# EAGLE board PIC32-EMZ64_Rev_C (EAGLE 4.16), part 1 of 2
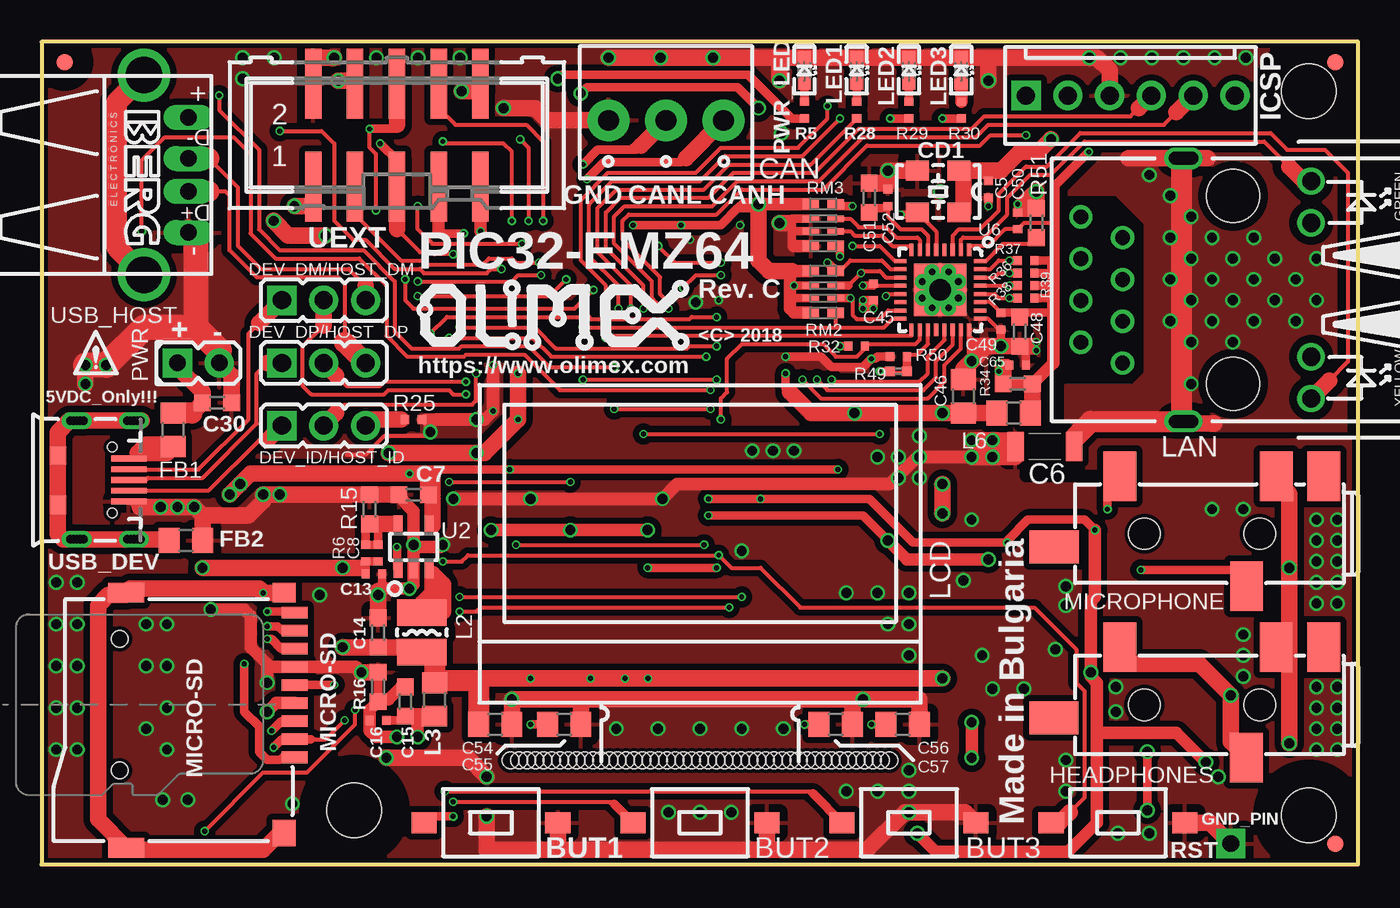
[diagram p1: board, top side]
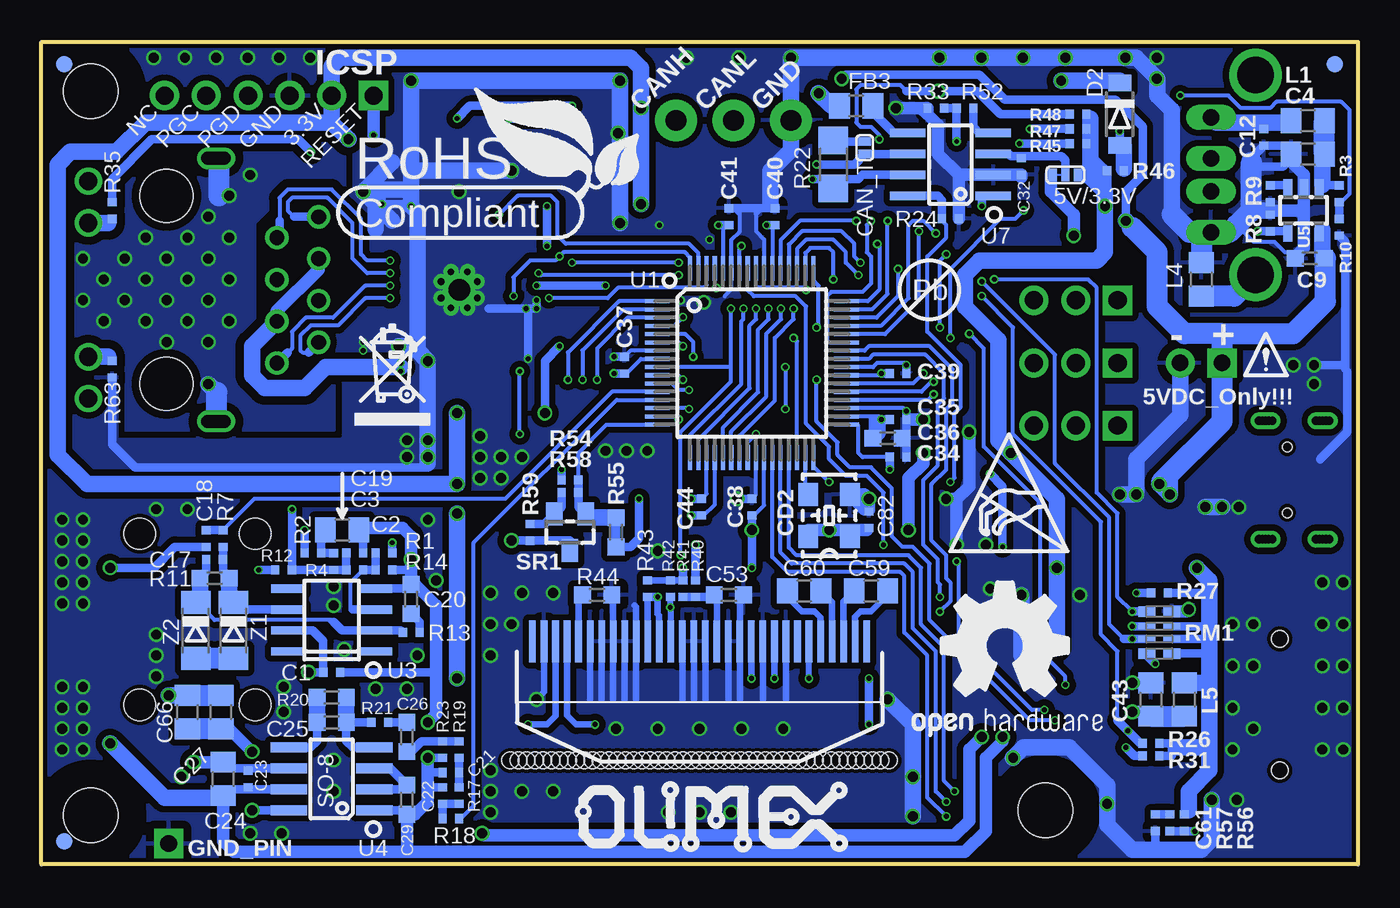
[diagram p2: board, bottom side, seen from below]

Size 80 x 50 mm. Coordinates in mm from the lower left corner, seen from the top.
Outline: 0,0 80,0 80,50 0,50 0,0
Copper layers (1*16): Top 0.035mm / dielectric 1.5mm / Bottom 0.035mm
Design rules "default": minimum track width 5mil, minimum drill 0.3mm, track to track 8mil, track to pad 8mil, pad to pad 8mil, via to via 8mil, smd to smd 1mil, copper to edge 10mil, drill to drill 8mil, minimum pad ring 10mil, minimum via ring 4mil, stop-mask expansion 4mil, vias tented up to drill 25mil, thermal gap 20mil
Net classes: 1 PWR: width 0.203 mm, drill 0.178 mm, clearance 0.381 mm; 2 thin: width 0.127 mm, drill 0.127 mm
Holes 3.3 mm at 19,3.3 77,3 77,47
tRestrict: area 74,44 to 80,50; area 16,0.3 to 22,6.3; area 74,0 to 80,6; 4 lines
bRestrict: area 16,0.3 to 22,6.3; area 74,0 to 80,6; area 74,44 to 80,50

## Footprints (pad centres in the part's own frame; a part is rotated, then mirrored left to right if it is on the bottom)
SJ_2_SMALLER_12_TIED = smd 0.508 x 0.762: 1 -0.762,0; 2 0,0; 3 0.762,0
WS-TAKT_6X3.5_SMD_NOCREAM = smd 1.27 x 1.524: P$1 0,4.064; P$2 0,-4.064
C0402_SMALL = smd 0.5 x 0.55: 1 -0.508,0; 2 0.508,0
C0805_5MIL_DWS = smd 1.27 x 1.524: 1 -1.016,0; 2 1.016,0
C1206_5MILS_WS_ISO = smd 1.016 x 1.778: 1 -1.778,0; 2 1.778,0
C0603_DWS = smd 1.016 x 1.016: 1 -0.889,0; 2 0.889,0
CON3/3.5MM = drill 1.27 pad 2.54 round: 1 -1.75,-0.5; 2 1.75,-0.5; 3 5.25,-0.5
SJ_1_SMALLER = smd 0.508 x 0.762: 1 -0.381,0; 2 0.381,0
5032-4P_HCX-3S = smd 1.4 x 1.2: 1 -1.27,-1.27; 2 1.27,-1.27; 3 1.27,1.27; 4 -1.27,1.27
SOD-123 = smd 1 x 1.4: A 1.9,0; C -1.9,0
JP2 = drill 1.1 pad 1.778 square: 1 -2.54,0 | drill 1.1 pad 1.778 round: 2 0,0; 3 2.54,0
L0805_5MIL_DWS = smd 1.27 x 1.524: 1 -1.016,0; 2 1.016,0
FIDUCIAL-1X3 = smd 1 x 1: 1 0,0
TEST_PAD40/70/SQUARE = drill 1.016 pad 1.778 square: P$1 0,0
PJ-W47S-05D2-LF_5PIN_V2 = smd 2 x 3: 1 2.1,-0.5; 2 14.5,-0.5; 3 6.8,6.2; 5 5,-0.5 | smd 3 x 2: 4 18.5,3.8 | hole 1.9: 6,3; 13,3
CON2.54MM-6-0D = drill 1.092 pad 1.778 square: 1 -6.35,0 | drill 1.092 pad 1.778 round: 2 -3.81,0; 3 -1.27,0; 4 1.27,0; 5 3.81,0; 6 6.35,0
CD32 = smd 1.6 x 3: 1 -1.2,0; 2 1.2,0
RJLBC-060TC1_MILLING = drill 0.9 round: 1 -4.455,6.7; 2 -3.185,9.24; 3 -1.915,6.7; 4 -0.645,9.24; 5 0.625,6.7; 6 1.895,9.24; 7 3.165,6.7; 8 4.435,9.24 | drill 0.8 round: _1 -8,2.5; _2 -8,2.7; _3 -8,2.9; _4 -8,3.3; _5 -8,3.5; _6 8,3.5; _7 8,3.3; _8 8,2.9; _9 8,2.7; _10 8,2.5; GND1 -8,3.1; GND2 8,3.1 | drill 1.1 round: AG 4.07,-4.748; AY -6.61,-4.748; KG 6.61,-4.748; KY -4.07,-4.748 | hole 3.2: -5.715,0; 5.715,0
IROP055-010-0128064-W(BOTTOM_CONTACTS_DRILLING) = smd 0.4 x 2.54 bottom: 1 -10.15,-6.77; 2 -9.45,-6.77; 3 -8.75,-6.77; 4 -8.05,-6.77; 5 -7.35,-6.77; 6 -6.65,-6.77; 7 -5.95,-6.77; 8 -5.25,-6.77; 9 -4.55,-6.77; 10 -3.85,-6.77; 11 -3.15,-6.77; 12 -2.45,-6.77; 13 -1.75,-6.77; 14 -1.05,-6.77; 15 -0.35,-6.77; 16 0.35,-6.77; 17 1.05,-6.77; 18 1.75,-6.77; 19 2.45,-6.77; 20 3.15,-6.77; 21 3.85,-6.77; 22 4.55,-6.77; 23 5.25,-6.77; 24 5.95,-6.77; 25 6.65,-6.77; 26 7.35,-6.77; 27 8.05,-6.77; 28 8.75,-6.77; 29 9.45,-6.77; 30 10.15,-6.77 | hole 1: -11,-14; -10.5,-14; -10,-14; -9.5,-14; -9,-14; -8.5,-14; -8,-14; -7.5,-14; -7,-14; -6.5,-14; -6,-14; -5.5,-14; -5,-14; -4.5,-14; -4,-14; -3.5,-14; -3,-14; -2.5,-14; -2,-14; -1.5,-14; -1,-14; -0.5,-14; 0,-14; 0.5,-14; 1,-14; 1.5,-14; 2,-14; 2.5,-14; 3,-14; 3.5,-14; 4,-14; 4.5,-14; 5,-14; 5.5,-14; 6,-14; 6.5,-14; 7,-14; 7.5,-14; 8,-14; 8.5,-14; 9,-14; 9.5,-14; 10,-14; 10.5,-14; 11,-14; -11.5,-14; 11.5,-14
LED-0603_TEST = smd 0.8 x 0.8: A 0.762,0; C -0.762,0
TFC-WPAPR-08 = smd 1.6 x 0.7: 1 -6.994,2.25; 2 -6.994,1.15; 3 -6.994,0.05; 4 -6.994,-1.05; 5 -6.994,-2.15; 6 -6.994,-3.25; 7 -6.994,-4.35; 8 -6.994,-5.45; 9 -6.994,-6.55 | smd 1.4 x 1.2: 10 -6.369,-7.75 | smd 1.4 x 1.6: 11 -6.369,6.85 | smd 2.2 x 1.2: 12 3.231,-7.75; 13 3.231,7.75 | hole 1: 3.631,-4.95; 3.631,3.05
HN1X2 = drill 1 pad 1.778 square: 1 -1.27,0 | drill 1 pad 1.778 round: 2 1.27,0
R0402_SMALL = smd 0.5 x 0.55: 1 -0.508,0; 2 0.508,0
R0603_5MIL_DWS = smd 1.016 x 1.016: 1 -0.889,0; 2 0.889,0
0603_0R = smd 1.016 x 1.016: 1 -0.889,0; 2 0.889,0
R1206_5MIL_WS = smd 1.651 x 1.778: 1 -1.46,0; 2 1.46,0
R0402_TI_0R = smd 0.61 x 0.584: 1 -0.508,0; 2 0.508,0
R_MATRIX_4 = smd 0.635 x 1.016: 1.1 -1.27,-0.762; 1.2 -1.27,0.762; 4.1 1.27,-0.762; 4.2 1.27,0.762 | smd 0.381 x 1.016: 2.1 -0.381,-0.762; 2.2 -0.381,0.762; 3.1 0.381,-0.762; 3.2 0.381,0.762
SOT-23 = smd 1.4 x 1: 1 1.1,-0.95; 2 1.1,0.95; 3 -1.1,0
TQFP64-1 = smd 0.25 x 1.5: 1 -3.75,-5.75; 2 -3.25,-5.75; 3 -2.75,-5.75; 4 -2.25,-5.75; 5 -1.75,-5.75; 6 -1.25,-5.75; 7 -0.75,-5.75; 8 -0.25,-5.75; 9 0.25,-5.75; 10 0.75,-5.75; 11 1.25,-5.75; 12 1.75,-5.75; 13 2.25,-5.75; 14 2.75,-5.75; 15 3.25,-5.75; 16 3.75,-5.75; 33 3.75,5.75; 34 3.25,5.75; 35 2.75,5.75; 36 2.25,5.75; 37 1.75,5.75; 38 1.25,5.75; 39 0.75,5.75; 40 0.25,5.75; 41 -0.25,5.75; 42 -0.75,5.75; 43 -1.25,5.75; 44 -1.75,5.75; 45 -2.25,5.75; 46 -2.75,5.75; 47 -3.25,5.75; 48 -3.75,5.75 | smd 1.5 x 0.25: 17 5.75,-3.75; 18 5.75,-3.25; 19 5.75,-2.75; 20 5.75,-2.25; 21 5.75,-1.75; 22 5.75,-1.25; 23 5.75,-0.75; 24 5.75,-0.25; 25 5.75,0.25; 26 5.75,0.75; 27 5.75,1.25; 28 5.75,1.75; 29 5.75,2.25; 30 5.75,2.75; 31 5.75,3.25; 32 5.75,3.75; 49 -5.75,3.75; 50 -5.75,3.25; 51 -5.75,2.75; 52 -5.75,2.25; 53 -5.75,1.75; 54 -5.75,1.25; 55 -5.75,0.75; 56 -5.75,0.25; 57 -5.75,-0.25; 58 -5.75,-0.75; 59 -5.75,-1.25; 60 -5.75,-1.75; 61 -5.75,-2.25; 62 -5.75,-2.75; 63 -5.75,-3.25; 64 -5.75,-3.75
SOT23-5 = smd 1.2 x 0.55: 1 1.3,-0.95; 2 1.3,0; 3 1.3,0.95; 4 -1.3,0.95; 5 -1.3,-0.95
SO08 = smd 0.508 x 2.032: 1 -1.905,-2.667; 2 -0.635,-2.667; 3 0.635,-2.667; 4 1.905,-2.667; 5 1.905,2.667; 6 0.635,2.667; 7 -0.635,2.667; 8 -1.905,2.667
SO-8 = smd 0.6 x 2.2: 1 -1.905,-2.6; 2 -0.635,-2.6; 3 0.635,-2.6; 4 1.905,-2.6; 5 1.905,2.6; 6 0.635,2.6; 7 -0.635,2.6; 8 -1.905,2.6
QFN-32(DRILLS) = smd 0.25 x 0.75: 1 -1.75,-2.425; 2 -1.25,-2.425; 3 -0.75,-2.425; 4 -0.25,-2.425; 5 0.25,-2.425; 6 0.75,-2.425; 7 1.25,-2.425; 8 1.75,-2.425; 17 1.75,2.425; 18 1.25,2.425; 19 0.75,2.425; 20 0.25,2.425; 21 -0.25,2.425; 22 -0.75,2.425; 23 -1.25,2.425; 24 -1.75,2.425 | smd 0.75 x 0.25: 9 2.425,-1.75; 10 2.425,-1.25; 11 2.425,-0.75; 12 2.425,-0.25; 13 2.425,0.25; 14 2.425,0.75; 15 2.425,1.25; 16 2.425,1.75; 25 -2.425,1.75; 26 -2.425,1.25; 27 -2.425,0.75; 28 -2.425,0.25; 29 -2.425,-0.25; 30 -2.425,-0.75; 31 -2.425,-1.25; 32 -2.425,-1.75 | drill 1.3 round: EP1 0,0 | drill 0.4 round: EP2 -0.5,1.1; EP3 0.5,1.1; EP4 1.1,0.5; EP5 1.1,-0.5; EP6 0.5,-1.1; EP7 -0.5,-1.1; EP8 -1.1,-0.5; EP9 -1.1,0.5 | smd 3.2 x 3.2: EXP_PAD 0,0
SO-08_THIN = smd 0.508 x 2.159: 1 -1.905,-2.603; 2 -0.635,-2.603; 3 0.635,-2.603; 4 1.905,-2.603; 5 1.905,2.603; 6 0.635,2.603; 7 -0.635,2.603; 8 -1.905,2.603
ML10_S = smd 1 x 4.25: 1 -5.08,-3.125; 2 -5.08,3.125; 3 -2.54,-3.125; 4 -2.54,3.125; 5 0,-3.125; 6 0,3.125; 7 2.54,-3.125; 8 2.54,3.125; 9 5.08,-3.125; 10 5.08,3.125
MICRO_USB_5P/F_TYPEB_DIP = smd 2.15 x 0.35: D+ -2,0; D- -2,-0.65; GND -2,1.3; ID -2,0.65; VBUS -2,-1.3 | drill 0.5 round: P$2 1.36,3.6; P$3 1.56,3.6; P$4 0.96,3.6; P$5 0.76,3.6; P$7 1.36,-3.6; P$8 1.56,-3.6; P$9 0.96,-3.6; P$10 0.76,-3.6; P$12 -2.11,3.6; P$13 -1.91,3.6; P$14 -2.51,3.6; P$15 -2.71,3.6; P$17 -2.11,-3.6; P$18 -1.91,-3.6; P$19 -2.51,-3.6; P$20 -2.71,-3.6; SH3 1.16,3.6; SH4 1.16,-3.6; SH5 -2.31,3.6; SH6 -2.31,-3.6 | smd 1 x 1.1: SH1 2.31,-1.5; SH2 2.31,1.5 | hole 0.55: -0.99,2; -0.99,-2
USB_PN87520_HOST_PTH = drill 1 long: 1 -3.5,2.71; 2 -1,2.71; 3 1,2.71; 4 3.5,2.71 | drill 2.2 round: P$1 6.07,0; P$2 -6.07,0
SOD80C = smd 1.4 x 1.8: A 1.7,0; C -1.7,0

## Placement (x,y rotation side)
5V/3.3V  5V:Closed/3.3V:Opened  [SJ_2_SMALLER_12_TIED]  17.78,41.91 0 bottom
BUT1  T1107A(6X3,8X2,5MM)  [WS-TAKT_6X3.5_SMD_NOCREAM]  27.3,2.54 90 top
BUT2  T1107A(6X3,8X2,5MM)  [WS-TAKT_6X3.5_SMD_NOCREAM]  40.01,2.54 90 top
BUT3  T1107A(6X3,8X2,5MM)  [WS-TAKT_6X3.5_SMD_NOCREAM]  52.7,2.54 90 top
C1  100nF  [C0402_SMALL]  62.36,11.68 0 bottom
C2  47uF/6.3V  [C0805_5MIL_DWS]  61.72,20.32 0 bottom
C3  100nF  [C0402_SMALL]  60.96,17.91 0 bottom
C4  47uF/6.3V  [C0805_5MIL_DWS]  3.05,43.18 180 bottom
C5  100nF  [C0402_SMALL]  57.53,41.02 270 top
C6  1nF/2kV/X7R/1206  [C1206_5MILS_WS_ISO]  60.96,25.4 0 top
C7  22uF/6.3V  [C0603_DWS]  22.61,22.48 180 top
C8  22pF  [C0402_SMALL]  20.45,18.92 90 top
C9  22uF/6.3V  [C0603_DWS]  2.92,36.83 180 bottom
C12  100nF  [C0402_SMALL]  5.71,44.2 270 bottom
C13  100nF  [C0402_SMALL]  20.19,17.65 0 top
C14  22uF/6.3V  [C0603_DWS]  20.45,14.1 90 top
C15  22uF/6.3V  [C0603_DWS]  22.1,9.91 90 top
C16  100nF  [C0402_SMALL]  20.45,8.76 180 top
C17  22pF  [C0402_SMALL]  69.47,18.54 180 bottom
C18  22pF  [C0402_SMALL]  69.98,19.81 270 bottom
C19  22pF  [C0402_SMALL]  60.96,18.92 0 bottom
C20  2.2uF/6.3V  [C0603_DWS]  57.53,16.13 90 bottom
C21  33nF  [C0402_SMALL]  55.12,5.59 180 bottom
C22  33nF  [C0402_SMALL]  55.63,4.19 90 bottom
C23  100nF  [C0402_SMALL]  67.44,5.21 270 bottom
C24  47uF/6.3V  [C0805_5MIL_DWS]  68.96,5.21 270 bottom
C25  470pF  [C0603_DWS]  62.36,8.64 0 bottom
C26  2.2uF/6.3V  [C0603_DWS]  57.78,7.75 270 bottom
C27  47uF/6.3V  [C0805_5MIL_DWS]  69.09,9.27 90 bottom
C29  2.2uF/6.3V  [C0603_DWS]  57.78,3.94 270 bottom
C30  22uF/6.3V  [C0603_DWS]  10.67,28.07 0 top
C32  100nF  [C0402_SMALL]  20.45,42.42 270 bottom
C34  100nF  [C0402_SMALL]  27.94,24.77 180 bottom
C35  100nF  [C0402_SMALL]  27.94,27.05 180 bottom
C36  22uF/6.3V  [C0603_DWS]  28.57,25.91 0 bottom
C37  100nF  [C0402_SMALL]  44.58,30.35 90 bottom
C38  100nF  [C0402_SMALL]  36.83,21.72 90 bottom
C39  100nF  [C0402_SMALL]  27.94,29.84 0 bottom
C40  100nF  [C0402_SMALL]  35.43,39.37 90 bottom
C41  100nF  [C0402_SMALL]  38.23,39.37 90 bottom
C43  47uF/6.3V  [C0805_5MIL_DWS]  12.57,10.03 90 bottom
C44  100nF  [C0402_SMALL]  39.88,21.72 270 bottom
C45  100nF  [C0402_SMALL]  50.55,34.8 90 top
C46  47uF/6.3V  [C0805_5MIL_DWS]  56.01,28.45 270 top
C48  22uF/6.3V  [C0603_DWS]  59.44,32.38 90 top
C49  100nF  [C0402_SMALL]  58.29,33.02 90 top
C50  100nF  [C0402_SMALL]  59.31,39.12 270 top
C51  2.2uF/6.3V  [C0603_DWS]  50.29,40.51 270 top
C52  100nF  [C0402_SMALL]  51.44,40.51 270 top
C53  NA(2.2uF/6.3V)  [C0603_DWS]  38.23,16.38 0 bottom
C54  1uF/16V  [C0805_5MIL_DWS]  27.56,8.51 180 top
C55  1uF/16V  [C0805_5MIL_DWS]  31.75,8.51 180 top
C56  10uF/16V  [C0805_5MIL_DWS]  52.32,8.51 180 top
C57  10uF/16V  [C0805_5MIL_DWS]  48.26,8.51 180 top
C59  1uF/16V  [C0805_5MIL_DWS]  29.59,16.64 180 bottom
C60  1uF/16V  [C0805_5MIL_DWS]  33.66,16.64 180 bottom
C61  100nF  [C0402_SMALL]  12.32,2.54 270 bottom
C65  100nF  [C0402_SMALL]  59.31,30.35 180 top
C66  47uF/6.3V  [C0805_5MIL_DWS]  71.12,9.27 90 bottom
C82  100nF  [C0402_SMALL]  29.72,20.95 90 bottom
CAN  TB3-3.5mm  [CON3/3.5MM]  36.2,45.72 0 top
CAN_T  Open  [SJ_1_SMALLER]  29.97,43.56 90 bottom
CD1  6NC2-50MHz(5032)  [5032-4P_HCX-3S]  54.48,40.89 180 top
CD2  F535L-24(24MHz/50ppm/5x3.2mm)  [5032-4P_HCX-3S]  32.13,21.21 90 bottom
D2  1N5819(S4SOD-123)  [SOD-123]  14.48,45.59 270 bottom
DEV_DM/HOST_DM  HN1x3(DEV_DM:Closed/DEV_DP:Opened)  [JP2]  17.14,34.29 0 top
DEV_DP/HOST_DP  HN1x3(DEV_DM:Closed/DEV_DP:Opened)  [JP2]  17.14,30.48 0 top
DEV_ID/HOST_ID  HN1x3(DEV_DM:Closed/DEV_DP:Opened)  [JP2]  17.14,26.67 0 top
FB1  FB0805/600R/2A  [L0805_5MIL_DWS]  8,26.42 270 top
FB2  FB0805/600R/2A  [L0805_5MIL_DWS]  8.76,19.68 180 top
FB3  FB0805/600R/2A  [L0805_5MIL_DWS]  30.48,46.1 180 bottom
FID1  FIDUCIAL  [FIDUCIAL-1X3]  78.61,48.77 90 top
FID2  FIDUCIAL  [FIDUCIAL-1X3]  78.61,1.27 90 top
FID3  FIDUCIAL  [FIDUCIAL-1X3]  1.4,48.77 90 top
FID4  FIDUCIAL  [FIDUCIAL-1X3]  1.4,48.64 0 bottom
FID5  FIDUCIAL  [FIDUCIAL-1X3]  78.61,48.64 0 bottom
FID6  FIDUCIAL  [FIDUCIAL-1X3]  78.61,1.4 0 bottom
GND_PIN  TESTPAD3  [TEST_PAD40/70/SQUARE]  72.26,1.27 0 top
HEADPHONES  PJ-W47S-05D2-LF_V2  [PJ-W47S-05D2-LF_5PIN_V2]  80.01,12.7 180 top
ICSP  WF6S  [CON2.54MM-6-0D]  66.17,46.74 0 top
L1  FB0805/600R/2A  [L0805_5MIL_DWS]  3.05,45.21 0 bottom
L2  2.2uH/1.5A/DCR<0.1R/CD32  [CD32]  23.11,14.1 270 top
L3  FB0805/600R/2A  [L0805_5MIL_DWS]  23.88,10.03 270 top
L4  FB0805/600R/2A  [L0805_5MIL_DWS]  9.53,35.56 270 bottom
L5  FB0805/600R/2A  [L0805_5MIL_DWS]  10.54,10.03 270 bottom
L6  FB0805/600R/2A  [L0805_5MIL_DWS]  59.05,27.43 180 top
LAN  RJLBC-060TC1  [RJLBC-060TC1_MILLING]  72.39,34.92 90 top
LCD  LCD_OLED_128X64(IROP055-010-0128064-W)  [IROP055-010-0128064-W(BOTTOM_CONTACTS_DRILLING)]  40.01,20.32 0 top
LED1  LED/Green/0603  [LED-0603_TEST]  49.53,48.26 270 top
LED2  LED/Yello/0603  [LED-0603_TEST]  52.7,48.26 270 top
LED3  LED/Red/0603  [LED-0603_TEST]  55.88,48.26 270 top
MICRO-SD  TFC-WPAPR-08  [TFC-WPAPR-08]  8.38,8.76 180 top
MICROPHONE  PJ-W47S-05D2-LF_V2  [PJ-W47S-05D2-LF_5PIN_V2]  80.02,23.11 180 top
PWR  NA(HN1X2)  [HN1X2]  9.53,30.48 0 top
PWR_LED  LED/Red/0603  [LED-0603_TEST]  46.35,48.26 270 top
R1  20k  [R0402_SMALL]  59.18,18.92 0 bottom
R2  330R  [R0402_SMALL]  63.5,18.92 180 bottom
R3  10k  [R0402_SMALL]  1.14,40.77 90 bottom
R4  10k  [R0402_SMALL]  62.23,18.41 90 bottom
R5  1k  [R0402_SMALL]  46.35,45.85 90 top
R6  4.99k/1%  [R0402_SMALL]  19.68,18.92 90 top
R7  330R  [R0402_SMALL]  68.96,19.81 90 bottom
R8  10k  [R0402_SMALL]  5.33,38.99 270 bottom
R9  13k/1%  [R0402_SMALL]  5.33,40.77 90 bottom
R10  20k  [R0402_SMALL]  1.14,38.73 90 bottom
R11  330k/1%  [R0603_5MIL_DWS]  69.47,17.4 0 bottom
R12  NA  [R0402_SMALL]  65.28,17.91 0 bottom
R13  13k/1%  [R0402_SMALL]  57.53,14.1 180 bottom
R14  20k  [R0402_SMALL]  59.18,17.91 180 bottom
R15  1.1k/1%  [R0603_5MIL_DWS]  19.94,21.59 90 top
R16  0R(Board_Mounted)  [0603_0R]  20.45,10.79 270 top
R17  1k  [R0402_SMALL]  54.61,4.19 90 bottom
R18  1k  [R0402_SMALL]  55.12,2.79 180 bottom
R19  10k  [R0402_SMALL]  54.61,6.99 270 bottom
R20  12.1k/1%  [R0603_5MIL_DWS]  62.36,10.16 180 bottom
R21  4.99k/1%  [R0402_SMALL]  59.44,8.64 180 bottom
R22  120R  [R1206_5MIL_WS]  31.88,42.55 270 bottom
R23  20k  [R0402_SMALL]  55.63,6.99 90 bottom
R24  10k  [R0402_SMALL]  24.77,39.24 180 bottom
R25  10k  [R0402_SMALL]  22.61,27.05 180 top
R26  10k  [R0402_SMALL]  12.57,7.37 0 bottom
R27  1k  [R0402_SMALL]  12.06,16.51 0 bottom
R28  1k  [R0402_SMALL]  49.53,45.85 270 top
R29  1k  [R0402_SMALL]  52.7,45.85 270 top
R30  1k  [R0402_SMALL]  55.88,45.85 270 top
R31  10k  [R0402_SMALL]  12.57,6.6 0 bottom
R32  2.2k  [R0402_SMALL]  49.53,31.5 180 top
R33  NA(2.2k)  [R0402_SMALL]  25.65,45.97 180 bottom
R34  0R(Board_Mounted)  [0603_0R]  59.31,29.21 0 top
R35  330R  [R0402_SMALL]  75.69,39.75 270 bottom
R36  49.9R/1%  [R0402_SMALL]  59.82,35.94 0 top
R37  49.9R/1%  [R0402_SMALL]  59.82,36.7 0 top
R38  49.9R/1%  [R0402_SMALL]  59.82,34.42 0 top
R39  49.9R/1%  [R0402_SMALL]  59.82,35.18 0 top
R40  330R  [R0402_SMALL]  40.26,16.76 270 bottom
R41  10k  [R0402_SMALL]  41.02,16.76 90 bottom
R42  2.2k  [R0402_SMALL]  41.78,16.76 90 bottom
R43  2.2k  [R0402_SMALL]  43.18,16.76 90 bottom
R44  330k/1%  [R0603_5MIL_DWS]  46.23,16.38 180 bottom
R45  2.2k  [R0402_SMALL]  17.02,43.81 0 bottom
R46  10k  [R0402_SMALL]  14.73,42.16 180 bottom
R47  2.2k  [R0402_SMALL]  17.02,44.7 0 bottom
R48  10k  [R0402_SMALL]  17.02,45.59 0 bottom
R49  0R(Board_Moiunted)  [R0402_TI_0R]  52.07,29.97 0 top
R50  4.7k  [R0402_SMALL]  52.07,30.86 0 top
R51  12.1k/1%  [R0603_5MIL_DWS]  60.45,38.99 270 top
R52  1k  [R0402_SMALL]  23.88,45.97 0 bottom
R54  NA  [R0402_SMALL]  47.88,23.37 180 bottom
R55  0R(Board_Mounted)  [0603_0R]  45.09,20.19 90 bottom
R56  4.7k  [R0402_SMALL]  10.54,2.54 270 bottom
R57  330R  [R0402_SMALL]  11.43,2.54 270 bottom
R58  NA  [R0402_SMALL]  47.88,22.61 0 bottom
R59  NA  [R0402_SMALL]  50.29,20.19 90 bottom
R63  330R  [R0402_SMALL]  75.69,30.1 270 bottom
RM1  RA1206_(4X0603)-100k  [R_MATRIX_4]  12.06,14.1 270 bottom
RM2  RA1206_(4X0603)_4B8_1.5k  [R_MATRIX_4]  47.5,34.8 270 top
RM3  RA1206_(4X0603)_4B8_1.5k  [R_MATRIX_4]  47.5,38.86 90 top
RST  T1107A(6X3,8X2,5MM)  [WS-TAKT_6X3.5_SMD_NOCREAM]  65.41,2.54 90 top
SR1  NA(AP431SA)  [SOT-23]  47.88,20.19 90 bottom
U1  PIC32MZ2048EFH064-I/PT(TQFP-64)  [TQFP64-1]  36.83,30.48 270 bottom
U2  SY8089AAAC(SOT23-5)  [SOT23-5]  22.61,19.3 270 top
U3  MCP601-I/SN(SO-8)  [SO08]  62.36,14.86 90 bottom
U4  TS4871(SO-8)  [SO-8]  62.36,5.21 90 bottom
U5  SY6280(SOT23-5)  [SOT23-5]  3.3,39.75 90 bottom
U6  LAN8710A-EZC  [QFN-32(DRILLS)]  54.61,34.92 180 top
U7  MCP2562-E/SN  [SO-08_THIN]  24.77,42.55 90 bottom
U$1  [ATTENTION_SMALL]  6.86,29.72 0 bottom
U$2  [ATTENTION_SMALL]  2.03,29.84 0 top
U$4  [OLIMEX1_V]  29.84,0.64 0 bottom
U$5  [PB_SMALL]  26.04,34.92 0 bottom
U$6  [RECYCLE_BIN1/8]  60.96,26.67 0 bottom
U$7  [ESD_SYMBOL]  24.77,19.05 0 bottom
U$8  [LOGO-OPENHARDWARE_8X8]  21.46,13.21 0 bottom
U$10  [ROHS]  60.96,38.73 0 bottom
U$11  [OLIMEX1_V]  40.51,31.11 0 top
UEXT  GBH-254-SMT-10  [ML10_S]  21.59,44.32 0 top
USB_DEV  USB_MicroB(MISB-SWMM-5B_LF)  [MICRO_USB_5P/F_TYPEB_DIP]  3.3,23.37 180 top
USB_HOST  USB_A  [USB_PN87520_HOST_PTH]  6.22,41.91 270 top
Z1  BZV55C2V4  [SOD80C]  68.33,14.22 270 bottom
Z2  BZV55C2V4  [SOD80C]  70.61,14.22 270 bottom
